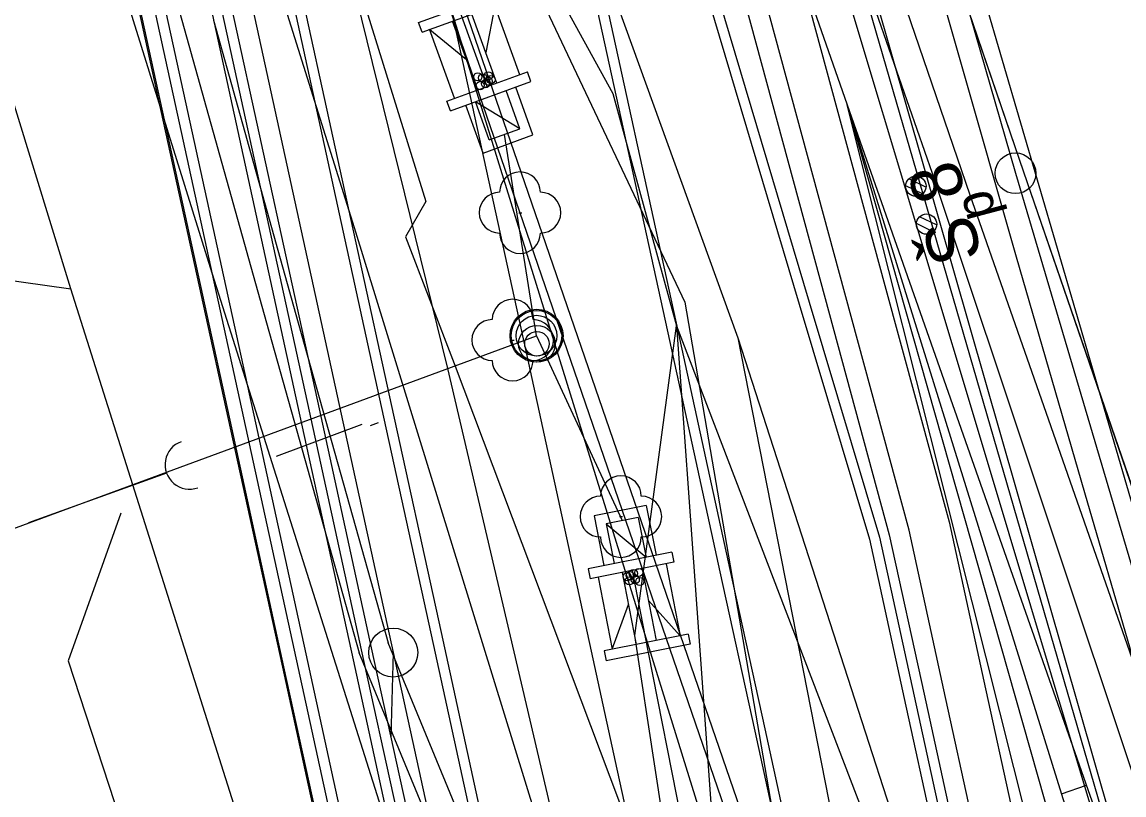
# Model space of a CAD drawing. Extents: x -440566 to -438466, y -1132677 to -1129707.
# Drawn here: x -439593.39 to -439566.37, y -1129976.63 to -1129957.67 of the extents above; entities that cross this region are included whole.
import ezdxf

# ---------------------------------------------------------------- set-up
doc = ezdxf.new("R2010")
doc.units = 0
for name, color, linetype in [('Vrstva 1', 7, 'Continuous'), ('Vrstva 10', 7, 'Continuous'), ('Vrstva 11', 7, 'Continuous'), ('Vrstva 15', 7, 'Continuous'), ('Vrstva 18', 7, 'Continuous'), ('Vrstva 20', 7, 'Continuous'), ('Vrstva 24', 7, 'Continuous'), ('Vrstva 25', 7, 'Continuous'), ('Vrstva 27', 7, 'Continuous'), ('Vrstva 36', 7, 'Continuous'), ('Vrstva 4', 7, 'Continuous'), ('Vrstva 42', 7, 'Continuous'), ('Vrstva 47', 7, 'Continuous'), ('Vrstva 49', 7, 'Continuous'), ('Vrstva 5', 7, 'Continuous'), ('Vrstva 50', 7, 'Continuous'), ('Vrstva 52', 7, 'Continuous'), ('Vrstva 57', 7, 'Continuous'), ('Vrstva 59', 7, 'Continuous'), ('Vrstva 61', 7, 'Continuous'), ('Vrstva 62', 7, 'Continuous'), ('Vrstva 63', 7, 'Continuous'), ('Vrstva 9', 7, 'Continuous')]:
    doc.layers.add(name, color=color, linetype=linetype)

# ---------------------------------------------------------------- blocks, each defined once
blk = doc.blocks.new('LAPAC_')
at = {"layer": 'Vrstva 1'}
for p, q in [((5, 10.49), (5, -10.5)), ((5, 10.49), (7.51, 10.49)), ((7.51, 10.49), (7.53, -10.5)), ((7.51, 8.5), (25.51, 8.49)), ((25.49, 8.48), (15.5, 2.5)), ((25.5, 10.47), (28, 10.48)), ((25.5, 10.47), (25.5, -10.5)), ((28, 10.48), (28.01, -10.48)), ((-7.5, 6.5), (4.99, 6.51)), ((-7.5, 6.5), (-7.49, -6.51)), ((-4.98, 4), (-5, -4)), ((-5, -4), (5, 4)), ((-4.98, 4), (5.01, 4)), ((7.51, 2.5), (25.5, 2.51)), ((7.51, 0), (28, 0)), ((7.51, -2.49), (25.5, -2.51)), ((25.51, -8.49), (15.52, -2.5)), ((-5, -4), (4.99, -4)), ((-7.49, -6.51), (4.99, -6.51)), ((5, -10.5), (7.53, -10.5)), ((7.51, -8.5), (25.51, -8.49)), ((25.5, -10.5), (28.01, -10.48))]:
    blk.add_line(p, q, dxfattribs=at)
for centre in [(8.3, 1.56), (8.3, 0.16), (8.67, -0.69), (9.89, 0.34), (10.54, 1.36), (8.76, -1.44), (9.88, -1.16)]:
    blk.add_circle(centre, 1, dxfattribs=at)

msp = doc.modelspace()

# ---------------------------------------------------------------- linework, layer by layer
at = {"layer": 'Vrstva 10'}
msp.add_line((-439567.29, -1129976.404), (-439567.902, -1129976.618), dxfattribs=at)
msp.add_lwpolyline([(-439606.718, -1129878.884), (-439599.16, -1129893.286), (-439591.48, -1129910.122), (-439589.662, -1129921.096), (-439588.348, -1129928.69), (-439584.254, -1129940.826), (-439581.56, -1129949.574), (-439575.832, -1129965.416), (-439572.088, -1129984.488)], dxfattribs=at)
at = {"layer": 'Vrstva 11'}
for p, q in [((-439585.23, -1129962.72), (-439590.882, -1129944.718)), ((-439592.188, -1129964.216), (-439594.19, -1129957.712)), ((-439595.506, -1129963.746), (-439592.188, -1129964.216))]:
    msp.add_line(p, q, dxfattribs=at)
for points in [[(-439631.45, -1129824.71), (-439623.296, -1129852.5), (-439607.812, -1129902.52), (-439594.486, -1129945.364), (-439588.77, -1129963.69), (-439582.318, -1129984.12), (-439576.384, -1130003.39), (-439571.028, -1130020.78), (-439569.524, -1130025.24)], [(-439572.89, -1130002.436), (-439578.954, -1129983.086), (-439585.23, -1129962.72)], [(-439579.544, -1130004.826), (-439579.646, -1130004.366), (-439585.608, -1129985.034), (-439592.188, -1129964.216)]]:
    msp.add_lwpolyline(points, dxfattribs=at)
at = {"layer": 'Vrstva 15'}
for p, q in [((-439571.222, -1129961.716), (-439571.638, -1129961.514)), ((-439571.308, -1129961.884), (-439571.718, -1129961.682)), ((-439571.044, -1129962.814), (-439571.456, -1129962.612)), ((-439570.96, -1129962.646), (-439571.376, -1129962.444))]:
    msp.add_line(p, q, dxfattribs=at)
for centre in [(-439571.47, -1129961.695), (-439571.207, -1129962.626)]:
    msp.add_circle(centre, 0.25, dxfattribs=at)
at = {"layer": 'Vrstva 18'}
msp.add_line((-439584.284, -1129973.139), (-439584.346, -1129975.199), dxfattribs=at)
msp.add_lwpolyline([(-439631.86, -1129744.036), (-439633.367, -1129748.063), (-439622.927, -1129795.938), (-439612.487, -1129843.813), (-439602.046, -1129891.688), (-439593.233, -1129932.103), (-439588.758, -1129952.621), (-439584.284, -1129973.139), (-439579.81, -1129993.657), (-439575.335, -1130014.174), (-439566.386, -1130055.21)], dxfattribs=at)
msp.add_circle((-439584.284, -1129973.139), 0.6, dxfattribs=at)
at = {"layer": 'Vrstva 20'}
msp.add_line((-439565.741, -1130069.199), (-439612.403, -1129855.228), dxfattribs=at)
msp.add_lwpolyline([(-439514.996, -1130118.198), (-439526.684, -1130084.16), (-439534.114, -1130062.498), (-439537.924, -1130051.384), (-439547.688, -1130022.904), (-439558.398, -1129991.686), (-439568.82, -1129961.348), (-439579.29, -1129930.716)], dxfattribs=at)
at = {"layer": 'Vrstva 24'}
for p, q in [((-439580.77, -1129965.363), (-439581.554, -1129960.424)), ((-439603.284, -1129973.676), (-439580.77, -1129965.363)), ((-439580.77, -1129965.363), (-439578.671, -1129969.901)), ((-439589.844, -1129968.733), (-439593.23, -1129969.957))]:
    msp.add_line(p, q, dxfattribs=at)
msp.add_arc((-439589.28, -1129968.529), 0.6, 109.8731, 289.8731, dxfattribs=at)
at = {"layer": 'Vrstva 25'}
for centre, radius in [((-439580.77, -1129965.363), 0.65), ((-439580.77, -1129965.363), 0.5), ((-439580.76, -1129965.562), 0.45), ((-439580.76, -1129965.562), 0.3)]:
    msp.add_circle(centre, radius, dxfattribs=at)
at = {"layer": 'Vrstva 27'}
msp.add_circle((-439580.77, -1129965.363), 0.62, dxfattribs=at)
at = {"layer": 'Vrstva 36'}
msp.add_line((-439573.97, -1129986.06), (-439607.88, -1129876.57), dxfattribs=at)
at = {"layer": 'Vrstva 4'}
for points in [[(-439452.672, -1130307.618), (-439463.136, -1130278.208), (-439473.444, -1130247.422), (-439485.028, -1130212.568), (-439496.122, -1130179.246), (-439507.47, -1130146.338), (-439516.97, -1130118.814), (-439528.894, -1130083.662), (-439539.69, -1130052.08), (-439549.11, -1130024.836), (-439560.748, -1129992.304), (-439571.06, -1129961.386), (-439580.88, -1129933.18), (-439592.05, -1129899.854), (-439602.118, -1129867.674), (-439610.398, -1129839.158), (-439617.774, -1129811.206), (-439624.664, -1129780.682), (-439629.998, -1129755.268)], [(-439452.072, -1130307.172), (-439462.466, -1130278.094), (-439473.084, -1130245.544), (-439484.196, -1130212.422), (-439495.494, -1130179.146), (-439506.764, -1130146.202), (-439516.426, -1130118.702), (-439528.244, -1130083.58), (-439539.098, -1130051.84), (-439548.434, -1130024.652), (-439559.722, -1129991.734), (-439570.14, -1129961.918), (-439579.974, -1129933.094), (-439590.708, -1129900.372), (-439601.098, -1129867.326), (-439609.248, -1129839.62), (-439616.746, -1129811.082), (-439623.958, -1129780.222), (-439629.3, -1129755.206)], [(-439595.111, -1129928.184), (-439592.98, -1129937.954), (-439590.85, -1129947.724), (-439588.719, -1129957.495), (-439586.588, -1129967.265), (-439585.31, -1129973.127), (-439584.458, -1129977.036), (-439582.327, -1129986.806), (-439580.196, -1129996.576), (-439578.066, -1130006.347), (-439575.935, -1130016.117), (-439573.804, -1130025.887), (-439571.674, -1130035.658), (-439570.166, -1130042.571), (-439569.543, -1130045.428), (-439567.412, -1130055.199), (-439565.282, -1130064.969), (-439563.151, -1130074.739), (-439561.02, -1130084.51), (-439558.89, -1130094.28), (-439556.759, -1130104.051), (-439554.628, -1130113.821)]]:
    msp.add_lwpolyline(points, dxfattribs=at)
at = {"layer": 'Vrstva 42'}
msp.add_lwpolyline([(-439399.158, -1130456.267), (-439407.226, -1130432.678), (-439417.232, -1130403.478), (-439427.682, -1130373.028), (-439438.464, -1130341.588), (-439448.942, -1130311.012), (-439450.914, -1130305.246), (-439460.972, -1130277.082), (-439482.918, -1130211.888), (-439494.254, -1130178.768), (-439505.592, -1130145.672), (-439514.996, -1130118.198), (-439526.684, -1130084.16), (-439534.114, -1130062.498), (-439537.924, -1130051.384), (-439547.688, -1130022.904), (-439558.398, -1129991.686), (-439568.82, -1129961.348), (-439575.094, -1129942.992)], dxfattribs=at)
at = {"layer": 'Vrstva 47'}
for p, q in [((-439577.344, -1129932.554), (-439569.026, -1129961.378)), ((-439569.026, -1129961.378), (-439560.537, -1129990.152))]:
    msp.add_line(p, q, dxfattribs=at)
msp.add_circle((-439569.026, -1129961.378), 0.5, dxfattribs=at)
at = {"layer": 'Vrstva 5'}
for points in [[(-439524.128, -1130104.684), (-439542.36, -1130053.899), (-439560.483, -1129998.857), (-439575.708, -1129945.714), (-439590.289, -1129890.237), (-439603.222, -1129834.191), (-439614.978, -1129781.165), (-439626.657, -1129727.981), (-439631.05, -1129707.012)], [(-439600.718, -1129837.291), (-439598.553, -1129847.054), (-439596.345, -1129856.808), (-439594.102, -1129866.554), (-439591.818, -1129876.291), (-439589.494, -1129886.019), (-439587.117, -1129895.735), (-439584.686, -1129905.44), (-439582.203, -1129915.134), (-439580.689, -1129920.945), (-439579.669, -1129924.816), (-439577.082, -1129934.487), (-439574.443, -1129944.147), (-439571.752, -1129953.795), (-439569.009, -1129963.432), (-439567.338, -1129969.208), (-439566.214, -1129973.057), (-439563.366, -1129982.671), (-439560.466, -1129992.274), (-439559.308, -1130002.256), (-439558.201, -1130012.25), (-439555.572, -1130021.911), (-439553.075, -1130031.602), (-439552.175, -1130035.027)], [(-439556.38, -1130040.02), (-439557.995, -1130032.675), (-439560.126, -1130022.905), (-439562.257, -1130013.134), (-439564.387, -1130003.364), (-439566.518, -1129993.593), (-439568.649, -1129983.823), (-439570.779, -1129974.053), (-439571.634, -1129970.132), (-439573.209, -1129964.322), (-439575.828, -1129954.658), (-439578.447, -1129944.994), (-439581.067, -1129935.33), (-439583.686, -1129925.667), (-439584.73, -1129921.813), (-439586.006, -1129915.963), (-439588.136, -1129906.193), (-439590.267, -1129896.422), (-439592.398, -1129886.652), (-439594.528, -1129876.882), (-439596.659, -1129867.111), (-439598.79, -1129857.341), (-439600.92, -1129847.57), (-439603.051, -1129837.8)], [(-439615.646, -1129839.184), (-439615.362, -1129840.485), (-439613.231, -1129850.255), (-439611.101, -1129860.025), (-439608.97, -1129869.796), (-439606.839, -1129879.566), (-439604.709, -1129889.337), (-439602.578, -1129899.107), (-439600.447, -1129908.877), (-439598.317, -1129918.648), (-439597.038, -1129924.51), (-439596.186, -1129928.418), (-439594.055, -1129938.188), (-439591.925, -1129947.959), (-439589.794, -1129957.729), (-439587.663, -1129967.5), (-439586.385, -1129973.362), (-439585.533, -1129977.27), (-439583.402, -1129987.04), (-439581.271, -1129996.811)], [(-439616.245, -1129839.315), (-439615.962, -1129840.616), (-439613.838, -1129850.388), (-439611.717, -1129860.16), (-439609.601, -1129869.933), (-439607.475, -1129879.705), (-439605.345, -1129889.475), (-439603.213, -1129899.246), (-439601.078, -1129909.015), (-439598.942, -1129918.784), (-439597.663, -1129924.646), (-439596.811, -1129928.554), (-439594.679, -1129938.325), (-439592.548, -1129948.095), (-439590.416, -1129957.865), (-439588.284, -1129967.635), (-439587.003, -1129973.497), (-439586.15, -1129977.405), (-439584.016, -1129987.174), (-439581.881, -1129996.944)], [(-439616.233, -1129839.312), (-439615.949, -1129840.613), (-439613.818, -1129850.383), (-439611.688, -1129860.154), (-439609.557, -1129869.924), (-439607.426, -1129879.694), (-439605.296, -1129889.465), (-439603.165, -1129899.235), (-439601.034, -1129909.005), (-439598.904, -1129918.776), (-439597.625, -1129924.638), (-439596.773, -1129928.546), (-439594.642, -1129938.317), (-439592.512, -1129948.087), (-439590.381, -1129957.857), (-439588.25, -1129967.628), (-439586.972, -1129973.49), (-439586.12, -1129977.398), (-439583.989, -1129987.168), (-439581.858, -1129996.939), (-439570.489, -1130045.839)], [(-439587.96, -1129916.389), (-439586.682, -1129922.251), (-439585.536, -1129926.096), (-439582.673, -1129935.706), (-439579.809, -1129945.317), (-439576.946, -1129954.927), (-439574.082, -1129964.538), (-439572.364, -1129970.304), (-439571.512, -1129974.212), (-439569.381, -1129983.983), (-439567.251, -1129993.753), (-439565.12, -1130003.524), (-439562.989, -1130013.294), (-439560.859, -1130023.064), (-439558.728, -1130032.835), (-439557.22, -1130039.748), (-439556.597, -1130042.605), (-439554.467, -1130052.375), (-439552.336, -1130062.146), (-439550.379, -1130071.121)], [(-439586.934, -1129922.311), (-439586.926, -1129922.305), (-439585.78, -1129926.149), (-439582.917, -1129935.76), (-439580.053, -1129945.37), (-439577.19, -1129954.981), (-439574.327, -1129964.591), (-439572.609, -1129970.358), (-439571.756, -1129974.266), (-439569.626, -1129984.036), (-439567.495, -1129993.806), (-439565.364, -1130003.577), (-439563.234, -1130013.347), (-439561.103, -1130023.118), (-439558.972, -1130032.888), (-439557.465, -1130039.801), (-439556.842, -1130042.658), (-439554.711, -1130052.429), (-439552.58, -1130062.199), (-439551.985, -1130064.928)], [(-439582.703, -1129925.478), (-439580.084, -1129935.142), (-439577.464, -1129944.805), (-439574.845, -1129954.469), (-439572.226, -1129964.133), (-439570.654, -1129969.931), (-439569.802, -1129973.84), (-439567.672, -1129983.61), (-439565.541, -1129993.38), (-439563.41, -1130003.151), (-439561.28, -1130012.921), (-439559.149, -1130022.691), (-439557.018, -1130032.462), (-439555.511, -1130039.375), (-439554.888, -1130042.232), (-439552.757, -1130052.003), (-439550.626, -1130061.773), (-439548.496, -1130071.543), (-439547.692, -1130075.226)], [(-439584.168, -1129925.797), (-439581.549, -1129935.461), (-439578.93, -1129945.125), (-439576.311, -1129954.789), (-439573.692, -1129964.453), (-439572.12, -1129970.251), (-439571.268, -1129974.159), (-439569.137, -1129983.93), (-439567.006, -1129993.7), (-439564.876, -1130003.47), (-439562.745, -1130013.241), (-439560.614, -1130023.011), (-439558.484, -1130032.781), (-439556.976, -1130039.694), (-439556.353, -1130042.552), (-439554.222, -1130052.322), (-439552.092, -1130062.093), (-439551.741, -1130063.699)], [(-439585.829, -1129926.16), (-439583.699, -1129935.93), (-439581.568, -1129945.7), (-439579.437, -1129955.471), (-439577.307, -1129965.241), (-439576.028, -1129971.103), (-439575.176, -1129975.011), (-439573.045, -1129984.782), (-439570.915, -1129994.552), (-439568.784, -1130004.323), (-439566.653, -1130014.093), (-439564.523, -1130023.863), (-439562.392, -1130033.634), (-439560.884, -1130040.547), (-439560.261, -1130043.404), (-439558.131, -1130053.174), (-439556, -1130062.945), (-439553.869, -1130072.715), (-439551.739, -1130082.486), (-439549.608, -1130092.256), (-439547.477, -1130102.026), (-439545.347, -1130111.797)], [(-439586.073, -1129926.213), (-439583.943, -1129935.983), (-439581.812, -1129945.754), (-439579.682, -1129955.524), (-439577.551, -1129965.294), (-439576.272, -1129971.157), (-439575.42, -1129975.065), (-439573.29, -1129984.835), (-439571.159, -1129994.605), (-439569.028, -1130004.376), (-439566.898, -1130014.146), (-439564.767, -1130023.917), (-439562.636, -1130033.687), (-439561.129, -1130040.6), (-439560.506, -1130043.457), (-439558.375, -1130053.228), (-439556.244, -1130062.998), (-439554.114, -1130072.769), (-439551.983, -1130082.539), (-439549.852, -1130092.309), (-439547.722, -1130102.08), (-439545.591, -1130111.85)], [(-439589.493, -1129926.959), (-439587.362, -1129936.729), (-439585.232, -1129946.499), (-439583.101, -1129956.27), (-439580.97, -1129966.04), (-439579.692, -1129971.902), (-439578.84, -1129975.81), (-439576.709, -1129985.581), (-439574.578, -1129995.351), (-439572.448, -1130005.122), (-439570.317, -1130014.892), (-439568.186, -1130024.662), (-439566.056, -1130034.433), (-439564.548, -1130041.346), (-439563.925, -1130044.203), (-439561.794, -1130053.973), (-439559.664, -1130063.744), (-439557.533, -1130073.514), (-439555.402, -1130083.285), (-439553.272, -1130093.055), (-439551.141, -1130102.825), (-439549.01, -1130112.596)], [(-439593.157, -1129927.758), (-439591.026, -1129937.528), (-439588.896, -1129947.298), (-439586.765, -1129957.069), (-439584.634, -1129966.839), (-439583.356, -1129972.701), (-439582.504, -1129976.609), (-439580.373, -1129986.38), (-439578.242, -1129996.15), (-439576.112, -1130005.921), (-439573.981, -1130015.691), (-439571.85, -1130025.461), (-439569.72, -1130035.232), (-439568.212, -1130042.145), (-439567.589, -1130045.002), (-439565.458, -1130054.772), (-439563.328, -1130064.543), (-439561.197, -1130074.313), (-439559.066, -1130084.084), (-439556.936, -1130093.854), (-439554.805, -1130103.624), (-439552.674, -1130113.395)], [(-439592.913, -1129927.704), (-439590.782, -1129937.475), (-439588.651, -1129947.245), (-439586.521, -1129957.015), (-439584.39, -1129966.786), (-439583.112, -1129972.648), (-439582.259, -1129976.556), (-439580.129, -1129986.327), (-439577.998, -1129996.097), (-439575.867, -1130005.867), (-439573.737, -1130015.638), (-439571.606, -1130025.408), (-439569.475, -1130035.178), (-439567.968, -1130042.091), (-439567.345, -1130044.949), (-439565.214, -1130054.719), (-439563.083, -1130064.49), (-439560.953, -1130074.26), (-439558.822, -1130084.03), (-439556.691, -1130093.801), (-439554.561, -1130103.571), (-439552.43, -1130113.341)], [(-439594.623, -1129928.077), (-439592.492, -1129937.848), (-439590.361, -1129947.618), (-439588.231, -1129957.388), (-439586.1, -1129967.159), (-439584.822, -1129973.021), (-439583.969, -1129976.929), (-439581.839, -1129986.699), (-439579.708, -1129996.47), (-439577.577, -1130006.24), (-439575.447, -1130016.011), (-439573.316, -1130025.781), (-439571.185, -1130035.551), (-439569.678, -1130042.464), (-439569.055, -1130045.322), (-439566.924, -1130055.092), (-439564.793, -1130064.862), (-439562.663, -1130074.633), (-439560.532, -1130084.403), (-439558.401, -1130094.174), (-439556.271, -1130103.944), (-439554.14, -1130113.714)], [(-439595.111, -1129928.184), (-439592.98, -1129937.954), (-439590.85, -1129947.724), (-439588.719, -1129957.495), (-439586.588, -1129967.265), (-439585.31, -1129973.127), (-439584.458, -1129977.036), (-439582.327, -1129986.806), (-439580.196, -1129996.576), (-439578.066, -1130006.347), (-439575.935, -1130016.117), (-439573.804, -1130025.887), (-439571.674, -1130035.658), (-439570.166, -1130042.571), (-439569.543, -1130045.428), (-439567.412, -1130055.199), (-439565.282, -1130064.969), (-439563.151, -1130074.739), (-439561.02, -1130084.51), (-439558.89, -1130094.28), (-439556.759, -1130104.051), (-439554.628, -1130113.821)], [(-439594.867, -1129928.13), (-439592.736, -1129937.901), (-439590.606, -1129947.671), (-439588.475, -1129957.442), (-439586.344, -1129967.212), (-439585.066, -1129973.074), (-439584.214, -1129976.982), (-439582.083, -1129986.753), (-439579.952, -1129996.523), (-439577.822, -1130006.293), (-439575.691, -1130016.064), (-439573.56, -1130025.834), (-439571.43, -1130035.605), (-439569.922, -1130042.518), (-439569.299, -1130045.375), (-439567.168, -1130055.145), (-439565.038, -1130064.916), (-439562.907, -1130074.686), (-439560.776, -1130084.456), (-439558.646, -1130094.227), (-439556.515, -1130103.997), (-439554.384, -1130113.768)]]:
    msp.add_lwpolyline(points, dxfattribs=at)
at = {"layer": 'Vrstva 50'}
for p, q in [((-439581.206, -1129962.346), (-439581.134, -1129962.346)), ((-439581.386, -1129965.47), (-439581.316, -1129965.47)), ((-439578.732, -1129969.804), (-439578.66, -1129969.804))]:
    msp.add_line(p, q, dxfattribs=at)
for centre, start, end in [((-439581.175, -1129961.845), 0, 180), ((-439581.675, -1129962.345), 90, 270), ((-439580.675, -1129962.345), 270, 90), ((-439581.175, -1129962.845), 180, 0), ((-439581.356, -1129964.97), 0, 180), ((-439581.856, -1129965.47), 90, 270), ((-439580.856, -1129965.47), 270, 90), ((-439581.356, -1129965.97), 180, 0), ((-439578.701, -1129969.303), 0, 180), ((-439579.201, -1129969.803), 90, 270), ((-439578.201, -1129969.803), 270, 90), ((-439578.701, -1129970.303), 180, 0)]:
    msp.add_arc(centre, 0.5, start, end, dxfattribs=at)
at = {"layer": 'Vrstva 52'}
for p, q in [((-439603.298, -1129908.222), (-439589.412, -1129957.822)), ((-439583.644, -1129950.788), (-439577.136, -1129964.538)), ((-439586.532, -1129951.596), (-439582.952, -1129966.168)), ((-439577.136, -1129964.538), (-439573.056, -1129988.268)), ((-439582.952, -1129966.168), (-439577.266, -1129990.506)), ((-439584.654, -1129967.502), (-439584.852, -1129967.576)), ((-439585.052, -1129967.544), (-439587.154, -1129968.328)), ((-439585.052, -1129967.544), (-439587.154, -1129968.328)), ((-439579.398, -1129985.038), (-439584.406, -1129972.9)), ((-439580.09, -1129985.324), (-439585.118, -1129973.142)), ((-439578.032, -1129973.138), (-439574.742, -1129989.788))]:
    msp.add_line(p, q, dxfattribs=at)
for points in [[(-439588.69, -1129957.62), (-439586.668, -1129964.842), (-439584.406, -1129972.9)], [(-439589.412, -1129957.822), (-439587.39, -1129965.044), (-439585.118, -1129973.142)]]:
    msp.add_lwpolyline(points, dxfattribs=at)
at = {"layer": 'Vrstva 57'}
msp.add_line((-439615.997, -1129861.04), (-439571.326, -1129991.012), dxfattribs=at)
at = {"layer": 'Vrstva 59'}
msp.add_line((-439615.666, -1129860.926), (-439570.995, -1129990.899), dxfattribs=at)
at = {"layer": 'Vrstva 61'}
msp.add_line((-439573.227, -1129945.323), (-439557.81, -1129998.142), dxfattribs=at)
at = {"layer": 'Vrstva 62'}
msp.add_line((-439560.603, -1129998.786), (-439575.875, -1129946.07), dxfattribs=at)
at = {"layer": 'Vrstva 63'}
msp.add_lwpolyline([(-439559.899, -1130001.173), (-439569.713, -1129968.453), (-439577.958, -1129940.931), (-439581.389, -1129927.721), (-439587.866, -1129899.446), (-439590.167, -1129890.323), (-439596.266, -1129862.915), (-439602.978, -1129834.556), (-439615.089, -1129778.896), (-439619.056, -1129758.708), (-439624.106, -1129738.276), (-439628.163, -1129719.403), (-439630.545, -1129707.012)], dxfattribs=at)
at = {"layer": 'Vrstva 9'}
for p, q in [((-439573.156, -1129959.7), (-439550.138, -1130025.226)), ((-439578.362, -1129972.718), (-439577.34, -1129965.12)), ((-439590.96, -1129969.718), (-439592.258, -1129973.346)), ((-439592.258, -1129973.346), (-439582.406, -1130003.292))]:
    msp.add_line(p, q, dxfattribs=at)
for points in [[(-439615.016, -1129861.902), (-439609.016, -1129872.388), (-439598.672, -1129902.048), (-439593.08, -1129922.412), (-439591.246, -1129928.438), (-439589.858, -1129932.272), (-439590.514, -1129935.246), (-439587.63, -1129940.776), (-439586.318, -1129945.922), (-439578.898, -1129959.416), (-439577.34, -1129965.12), (-439572.6, -1129977.504), (-439565.568, -1129996.93)], [(-439583.996, -1129927.66), (-439580.782, -1129937.88), (-439573.156, -1129959.7)], [(-439588.27, -1129946.636), (-439583.488, -1129962.072), (-439583.98, -1129962.938), (-439582.788, -1129966.044), (-439577.788, -1129979.34), (-439572.16, -1129999.082), (-439566.194, -1130018.824), (-439554.92, -1130053.378)], [(-439539.976, -1130066.112), (-439543.636, -1130055.94), (-439548.718, -1130040.922), (-439555.81, -1130018.284), (-439563.966, -1129996.25), (-439573.156, -1129959.7)], [(-439573.156, -1129959.7), (-439562.928, -1129995.746), (-439555.81, -1130018.284)], [(-439573.156, -1129959.7), (-439561.968, -1129995.718), (-439554.008, -1130017.84), (-439547.068, -1130040.406), (-439541.34, -1130055.714), (-439538.356, -1130063.796)], [(-439577.34, -1129965.12), (-439576.34, -1129978.998), (-439570.26, -1129998.734), (-439564.65, -1130018.494)], [(-439575.832, -1129965.416), (-439568.974, -1129986.65), (-439562.208, -1130006.75), (-439555.4, -1130027.656), (-439549.7, -1130045.104), (-439543.224, -1130064.878), (-439534.136, -1130092.886), (-439531.324, -1130101.162), (-439529.482, -1130100.572)], [(-439554.92, -1130053.378), (-439565.49, -1130018.736), (-439571.516, -1129998.944), (-439577.362, -1129979.234), (-439578.362, -1129972.718)]]:
    msp.add_lwpolyline(points, dxfattribs=at)

# ---------------------------------------------------------------- block references
at = {"layer": 'Vrstva 25'}
for p, xscale, yscale, rotation in [((-439581.724, -1129959.955), 0.09999999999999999, 0.1, 109.89937035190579), ((-439578.575, -1129970.389), 0.1, 0.10000000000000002, -78.79788058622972)]:
    msp.add_blockref('LAPAC_', p, dxfattribs=dict(at, xscale=xscale, yscale=yscale, rotation=rotation))

# ---------------------------------------------------------------- texts
at = {"layer": 'Vrstva 49'}
for s, height, p in [('Š 8', 1.25, (-439569.832, -1129963.418)), ('p', 0.938, (-439569.48, -1129962.398))]:
    msp.add_text(s, height=height, rotation=104.8992, dxfattribs=at).set_placement(p)

doc.saveas('drawing.dxf')
